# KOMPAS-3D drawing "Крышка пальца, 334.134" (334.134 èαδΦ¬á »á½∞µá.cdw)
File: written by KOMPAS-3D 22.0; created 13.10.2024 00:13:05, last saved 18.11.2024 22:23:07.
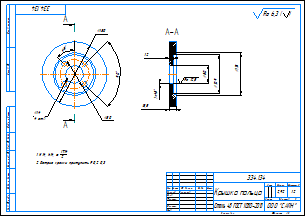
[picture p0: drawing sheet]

Sheet 1: A3, landscape

Document properties: Автор: aleksander.larionov.10@gmail.com; Полное имя файла: C:\Мои папки\Работа\Крышки, фланцы\334.134\334.134 Крышка пальца.cdw; Знак неуказанной шероховатости: 4; Параметр неуказанной шероховатости: Ra 6,3; Масса: 2.920453

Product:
- Part/product: Крышка пальца  | designation 334.134
    Материал: Сталь 45 ГОСТ 1050-2013 (density 7810 kg/m3)
    Масса: 2.920453

Title block, sheet 1: Наименование: Крышка пальца; designation: 334.134; Материал: Сталь 45 ГОСТ 1050-2013; Масса: 2,92; Количество листов документа: 1; organisation: ООО "САЙН"; Форматы листов документа: A3; stored path: C:\Users\aleks\Desktop\Работа\334.134 Крышка пальца.cdw; Разработал: Ларионов

Views: Вид 1, Сверху, Разрез 2, Разрез А-А
Referenced files in C:\Users\aleks\Desktop\Работа\: 334.134 Крышка пальца.m3d
Referenced files in C:\Мои папки\Работа\Крышки, фланцы\334.134\: 334.134 Крышка пальца.m3d
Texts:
  2 Острые кромки притупить R0,2...0,3.
  Ra 12,5
  Ra 6,3
  Ra 6,3 ( )
Dimensions and other numbers on the sheet: 180; 14; 4 отв.; 1 H14, h14,    IT14 2 .; 80; 334.134; 18,5; 12; 50; 109; 118; 1; 1:2; 2,92; 334.134 Крышка пальца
